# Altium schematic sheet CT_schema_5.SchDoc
size 287 x 160 mm
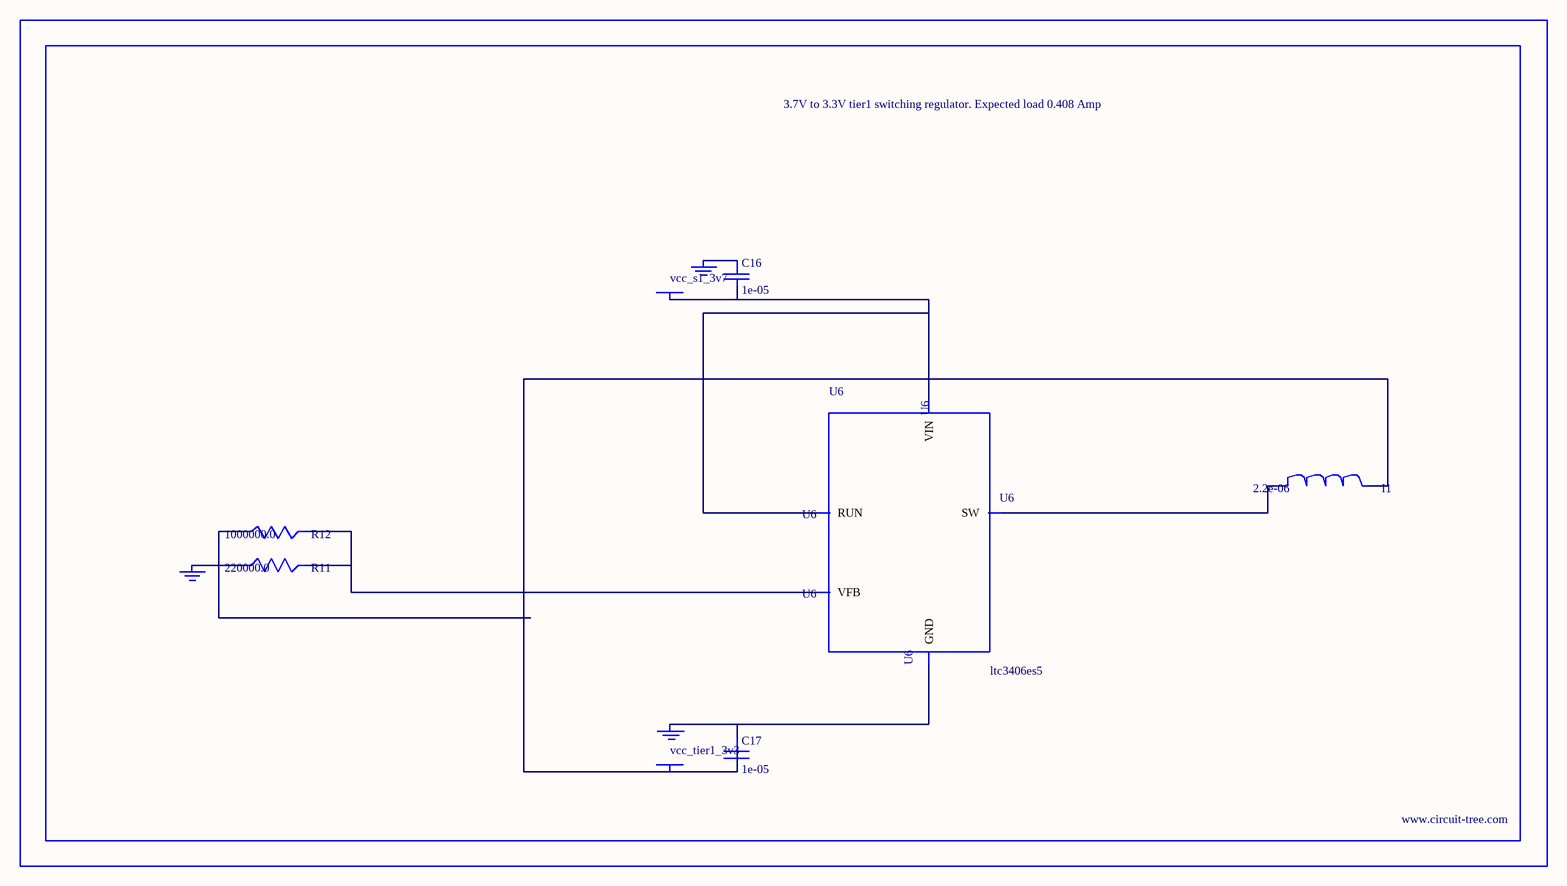
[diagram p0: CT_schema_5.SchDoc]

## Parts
BORDER4  (no value)
C16  1e-05  [C0805]
C17  1e-05  [C0805]
GND_INSTANCE_4_0  (no value)
GND_INSTANCE_4_1  (no value)
GND_INSTANCE_4_2  (no value)
I1  2.2e-06  [L0805]
POWER_INSTANCE_4_0  vcc_tier1_3v3
POWER_INSTANCE_4_1  vcc_s1_3v7
R11  220000.0  [R0603]
R12  1000000.0  [R0603]
U6  ltc3406es5  [TSOT-23-5]

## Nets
NetC16_1: C16.1 GND_INSTANCE_4_1.0(GND)
NetC16_2: C16.2 POWER_INSTANCE_4_1.0(PWR) U6.1(RUN) U6.4(VIN)
NetC17_1: C17.1 GND_INSTANCE_4_0.0(GND) U6.2(GND)
NetC17_2: C17.2 I1.2 POWER_INSTANCE_4_0.0(PWR) R12.1
NetGND_INSTANCE_4_2_0: GND_INSTANCE_4_2.0(GND) R11.1
NetI1_1: I1.1 U6.3(SW)
NetR11_2: R11.2 R12.2 U6.5(VFB)

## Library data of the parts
BORDER4 = BORDER_PAGE4
C16 C17 = C0805C106K8RACTU
GND_INSTANCE_4_0-GND_INSTANCE_4_2 = GND
I1 = L0805C2R2MDWIT
POWER_INSTANCE_4_0 POWER_INSTANCE_4_1 = PWR
R11 = RC0603JR-07220KL
R12 = RC0603JR-071ML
